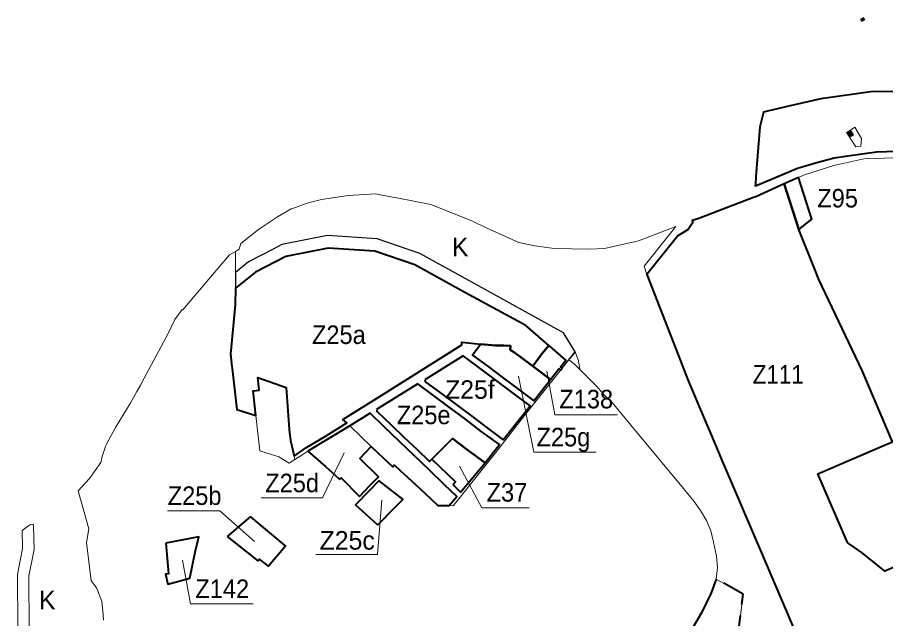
# Model space of a CAD drawing. Extents: x -650276 to -642489, y -1074425 to -1066658.
# Drawn here: x -650276 to -649154, y -1069854 to -1069075 of the extents above; entities that cross this region are included whole.
import ezdxf

# ---------------------------------------------------------------- set-up
doc = ezdxf.new("R2010")
doc.units = 0
doc.header["$LTSCALE"] = 9.6
doc.linetypes.add('MEDIUM_DASHED', pattern=[4.5, 3, -1.5])
for name, color, linetype, lineweight in [('1', 7, 'Continuous', 13), ('4', 7, 'Continuous', 40), ('42', 7, 'Continuous', 25), ('43', 7, 'Continuous', 13), ('44', 7, 'Continuous', 40), ('45', 7, 'Continuous', 40), ('46', 7, 'Continuous', 13), ('47', 7, 'Continuous', 13), ('61', 7, 'MEDIUM_DASHED', 40)]:
    doc.layers.add(name, color=color, linetype=linetype, lineweight=lineweight)

msp = doc.modelspace()

# ---------------------------------------------------------------- hatches: boundary and pattern name
at = {"layer": '1'}
for points in [[(-649180.56, -1069078.55), (-649182.45, -1069075.37), (-649186.32, -1069077.67), (-649184.43, -1069080.85)], [(-649199.29, -1069230.06), (-649195.38, -1069227.23), (-649199.26, -1069221.16), (-649203.42, -1069223.85)]]:
    msp.add_hatch(color=256, dxfattribs=at).paths.add_polyline_path(points)

# ---------------------------------------------------------------- linework, layer by layer
for points in [[(-649180.56, -1069078.55), (-649182.45, -1069075.37), (-649186.32, -1069077.67), (-649184.43, -1069080.85)], [(-649199.29, -1069230.06), (-649195.38, -1069227.23), (-649199.26, -1069221.16), (-649203.42, -1069223.85)]]:
    msp.add_lwpolyline(points, close=True, dxfattribs=at)
for points in [[(-649199.258, -1069221.162), (-649195.38, -1069227.23), (-649199.29, -1069230.06), (-649203.42, -1069223.85)], [(-649191.99, -1069242.79), (-649185.55, -1069242.21), (-649185.05, -1069232.01), (-649193.51, -1069217.45), (-649199.258, -1069221.162)], [(-649203.42, -1069223.85), (-649204.21, -1069224.36), (-649191.99, -1069242.79)], [(-649142.11, -1069257.07), (-649181.7, -1069258.52), (-649220.57, -1069266.88), (-649258.6, -1069279.34), (-649266.331, -1069282.804), (-649249.069, -1069336.66), (-649265.774, -1069350.068), (-649240.202, -1069414.528), (-649184.1, -1069532.2), (-649144.57, -1069624.6), (-649241.11, -1069665.9), (-649202.99, -1069754.99), (-649200.64, -1069756.53), (-649184.05, -1069768.45), (-649154.76, -1069792.11), (-649085.41, -1069762.44)], [(-649700.42, -1069691.8), (-649712.64, -1069707.43), (-649732.52, -1069706.92), (-649788.91, -1069654.4), (-649791.3, -1069657.21), (-649818.71, -1069630.64), (-649846.38, -1069603.8), (-649900.64, -1069636.78), (-649907.07, -1069640.92), (-649917.38, -1069647.56), (-649924.8, -1069652.19), (-649938.2, -1069644.23), (-649962.71, -1069636.46), (-649967.81, -1069590.74), (-649992.59, -1069582.88), (-649998.5, -1069529.88), (-650000.59, -1069511.15), (-649994.26, -1069444.75), (-649994.329, -1069405.451), (-649994.38, -1069378.33), (-650002.11, -1069382.8), (-650026.33, -1069411.47), (-650057.49, -1069448.18), (-650062.17, -1069454.05), (-650063.12, -1069453.54), (-650072.5, -1069466.44), (-650081.29, -1069484.35), (-650112.18, -1069542.11), (-650117.19, -1069551.46), (-650121.59, -1069559.59), (-650125.94, -1069567.19), (-650130.57, -1069575.27), (-650149.19, -1069606.26), (-650152.96, -1069612.53), (-650160.4, -1069626.97), (-650162.1, -1069630.49), (-650163.17, -1069633.49), (-650166.77, -1069643.52), (-650168.4, -1069651.27), (-650182.78, -1069672.09), (-650197.7, -1069688.08), (-650183.73, -1069737.28), (-650186.91, -1069755.15), (-650180.63, -1069804.63), (-650176.1, -1069810.74), (-650173.87, -1069813.75), (-650172.79, -1069816.55), (-650167.17, -1069831.25), (-650165.14, -1069847.93), (-650165.06, -1069855.42)], [(-649406.53, -1069871.59), (-649391.86, -1069846.18), (-649379.19, -1069820.24), (-649372.56, -1069802.33), (-649370.94, -1069787.45), (-649372.2, -1069772.58), (-649376.01, -1069754.58), (-649379.49, -1069740.04), (-649385.25, -1069726.48), (-649392.85, -1069713.53), (-649401.77, -1069701.47), (-649415.12, -1069685.26), (-649474.46, -1069613.59), (-649507.23, -1069573.85), (-649517.81, -1069563.27), (-649527.84, -1069552.16), (-649538.49, -1069541.54), (-649549.69, -1069530.14), (-649556.25, -1069523.62), (-649563.306, -1069518.507), (-649620.45, -1069590.75), (-649658.13, -1069638.84), (-649700.42, -1069691.8)], [(-649917.38, -1069647.56), (-649918.35, -1069643.45), (-649923.17, -1069623.14), (-649924.62, -1069608.53), (-649927.3, -1069572.44), (-649928.48, -1069554.57), (-649965.26, -1069541.51), (-649963.43, -1069557.91), (-649971.38, -1069558.79), (-649967.81, -1069590.74), (-649962.71, -1069636.46)], [(-649962.71, -1069636.46), (-649938.2, -1069644.23), (-649924.8, -1069652.19), (-649917.38, -1069647.56)]]:
    msp.add_lwpolyline(points, dxfattribs=at)
at = {"layer": '4'}
for points in [[(-649571.94, -1069529.24), (-649573.922, -1069527.657), (-649567, -1069519), (-649588, -1069501), (-649589.257, -1069499.905), (-649597.935, -1069510.728)], [(-649597.997, -1069510.805), (-649598.004, -1069510.814), (-649609.93, -1069526.87), (-649586.82, -1069544.11)], [(-649597.935, -1069510.728), (-649597.763, -1069510.865), (-649597.997, -1069510.805)], [(-649586.82, -1069544.11), (-649576.071, -1069530.398), (-649574.1, -1069531.97), (-649571.94, -1069529.24)], [(-650053.2, -1069801.11), (-650046.28, -1069767.47), (-650041.591, -1069747.598), (-650084.48, -1069755.86)], [(-650084.48, -1069755.86), (-650082.63, -1069775.78), (-650080.78, -1069795.7), (-650084.63, -1069796.06), (-650081.66, -1069808.87), (-650053.2, -1069801.11)]]:
    msp.add_lwpolyline(points, dxfattribs=at)
at = {"layer": '4', "lineweight": 13}
for points in [[(-649500.234, -1069589.798), (-649581.154, -1069589.798), (-649591.594, -1069533.245)], [(-649971.531, -1069834.438), (-650052.451, -1069834.438), (-650062.891, -1069777.884)]]:
    msp.add_lwpolyline(points, dxfattribs=at)
at = {"layer": '42'}
msp.add_lwpolyline([(-649561.91, -1069516.78), (-649555.16, -1069508.07), (-649570.03, -1069483.83), (-649688.625, -1069418.156), (-649755.971, -1069381.179), (-649810.846, -1069362.154), (-649875.434, -1069357.751), (-649934.363, -1069369.537), (-649945.397, -1069375.277), (-649977.239, -1069391.714), (-649994.329, -1069405.451), (-649994.293, -1069425.949), (-649994.53, -1069447.61), (-650000.59, -1069511.15), (-649992.59, -1069582.88), (-649967.81, -1069590.74), (-649971.38, -1069558.79), (-649963.43, -1069557.91), (-649965.26, -1069541.51), (-649928.48, -1069554.57), (-649924.62, -1069608.53), (-649923.17, -1069623.14), (-649918.35, -1069643.45), (-649903.292, -1069632.541), (-649877.129, -1069617.006), (-649850.24, -1069600.295), (-649855.34, -1069595.8), (-649805.22, -1069564.32), (-649701.57, -1069499.21), (-649701.7, -1069495.89), (-649677.02, -1069498.32), (-649658.01, -1069500.19), (-649647.45, -1069500.23), (-649638.81, -1069500.26), (-649639.18, -1069505.96), (-649628.36, -1069513.11), (-649609.93, -1069526.87), (-649598.004, -1069510.814), (-649589.257, -1069499.905), (-649567, -1069519), (-649573.922, -1069527.657), (-649571.94, -1069529.24), (-649555.16, -1069508.07)], close=True, dxfattribs=at)
at = {"layer": '44'}
msp.add_lwpolyline([(-649076.02, -1069172.683), (-649169.781, -1069171.432), (-649237.512, -1069180.731), (-649277.021, -1069189.913), (-649306.455, -1069196.754), (-649311.633, -1069197.958), (-649316.47, -1069216.91), (-649321.32, -1069281.47), (-649322.09, -1069291.73), (-649322.22, -1069293.54), (-649319.72, -1069292.47), (-649267.5, -1069270.41), (-649242.5, -1069263.3), (-649220.18, -1069257.03), (-649202.63, -1069254.4), (-649165.62, -1069249.43), (-649139.63, -1069248.73)], dxfattribs=at)
msp.add_lwpolyline([(-649265.774, -1069350.068), (-649249.069, -1069336.66), (-649266.331, -1069282.804), (-649284.695, -1069291.033)], close=True, dxfattribs=at)
at = {"layer": '45'}
for points in [[(-649099.75, -1069768.575), (-649154.76, -1069792.11), (-649184.05, -1069768.45), (-649200.64, -1069756.53), (-649202.99, -1069754.99), (-649241.11, -1069665.9), (-649155.082, -1069629.097), (-649144.57, -1069624.6), (-649184.1, -1069532.2), (-649240.202, -1069414.528), (-649244.08, -1069404.753), (-649265.774, -1069350.068), (-649284.695, -1069291.033), (-649321.69, -1069307.61), (-649324.3, -1069308.59), (-649359.48, -1069321.82), (-649389.4, -1069333.35), (-649396.52, -1069336.09), (-649403.92, -1069338.26), (-649403.03, -1069340.66), (-649408.81, -1069349.89), (-649422.19, -1069357.99), (-649462.25, -1069408.32), (-649435.578, -1069476.772), (-649435.578, -1069476.772), (-649431.761, -1069486.57), (-649416.52, -1069525.68), (-649409.355, -1069544.517), (-649388.438, -1069594.296), (-649379.32, -1069615.71), (-649364.44, -1069650.55), (-649312.03, -1069773.33), (-649246.81, -1069926.27)], [(-649639.18, -1069505.96), (-649637.69, -1069506.15), (-649628.36, -1069513.11), (-649609.93, -1069526.87), (-649598.004, -1069510.814), (-649589.257, -1069499.905), (-649619, -1069474), (-649697.525, -1069431.522), (-649762.488, -1069395.854), (-649814.067, -1069377.972), (-649874.391, -1069373.859), (-649929.015, -1069384.784), (-649968.465, -1069405.189), (-649994.293, -1069425.949), (-649994.53, -1069447.61), (-650000.59, -1069511.15), (-649998.81, -1069527.07), (-649998.5, -1069529.88), (-649992.59, -1069582.88), (-649967.81, -1069590.74), (-649971.38, -1069558.79), (-649963.43, -1069557.91), (-649965.26, -1069541.51), (-649928.48, -1069554.57), (-649927.3, -1069572.44)], [(-649927.3, -1069572.44), (-649924.62, -1069608.53), (-649923.17, -1069623.14), (-649918.35, -1069643.45), (-649918.35, -1069643.45), (-649903.292, -1069632.541), (-649877.129, -1069617.006), (-649850.24, -1069600.295), (-649855.34, -1069595.8), (-649805.22, -1069564.32), (-649801.49, -1069561.98), (-649701.57, -1069499.21), (-649701.7, -1069495.89), (-649677.02, -1069498.32), (-649658.01, -1069500.19), (-649647.45, -1069500.23), (-649638.81, -1069500.26), (-649639.18, -1069505.96)], [(-649677.02, -1069498.32), (-649687.77, -1069512.44), (-649667.74, -1069527.4), (-649649.31, -1069541.16)], [(-649639.18, -1069505.96), (-649638.81, -1069500.26), (-649647.45, -1069500.23), (-649658.01, -1069500.19), (-649677.02, -1069498.32)], [(-649609.93, -1069526.87), (-649628.36, -1069513.11), (-649637.69, -1069506.15), (-649639.18, -1069505.96)], [(-649707.19, -1069577.81), (-649688.76, -1069591.57), (-649670.34, -1069605.34), (-649647.93, -1069622.07), (-649628.8, -1069597.67), (-649613.37, -1069577.98), (-649636.83, -1069560.47), (-649659.26, -1069543.71), (-649681.7, -1069526.96), (-649699.72, -1069513.5), (-649722.6, -1069527.61), (-649749.62, -1069544.29)], [(-649649.31, -1069541.16), (-649630.88, -1069554.92), (-649608.44, -1069571.69), (-649586.82, -1069544.11), (-649609.93, -1069526.87)], [(-649749.62, -1069544.29), (-649748.89, -1069546.2), (-649747.5, -1069547.71), (-649725.62, -1069564.05), (-649707.19, -1069577.81)], [(-649758.29, -1069549.64), (-649785.72, -1069566.56), (-649812.08, -1069582.83)], [(-649671.39, -1069651.93), (-649652.88, -1069628.36), (-649677.124, -1069610.681), (-649696.91, -1069595.47), (-649718.13, -1069579.63), (-649739.75, -1069563.48), (-649758.29, -1069549.64)], [(-649788.91, -1069654.4), (-649781.09, -1069661.69), (-649761.34, -1069680.08), (-649741.61, -1069698.46), (-649732.52, -1069706.92), (-649717.884, -1069707.295), (-649707.985, -1069695.508), (-649723.97, -1069680.13), (-649743.41, -1069661.43), (-649762.85, -1069642.73), (-649782.03, -1069624.28), (-649801.48, -1069605.57), (-649820.02, -1069587.73), (-649846.38, -1069603.8), (-649900.64, -1069636.78)], [(-649812.08, -1069582.83), (-649811.52, -1069584.44), (-649810.49, -1069585.81), (-649793.12, -1069602.51), (-649776.54, -1069618.46), (-649759.97, -1069634.4)], [(-649740.23, -1069647.14), (-649713.73, -1069620.32), (-649713.73, -1069620.32), (-649693.63, -1069635.33), (-649671.39, -1069651.93)], [(-649900.64, -1069636.78), (-649877.82, -1069656.83), (-649859.96, -1069672.53)], [(-649833.94, -1069695.239), (-649819.98, -1069680.92), (-649809.47, -1069670.13), (-649833.38, -1069646.08), (-649818.71, -1069630.64)], [(-649818.71, -1069630.64), (-649802.9, -1069645.96), (-649791, -1069657), (-649788.91, -1069654.4)], [(-649759.97, -1069634.4), (-649743.39, -1069650.35), (-649740.23, -1069647.14)], [(-649859.96, -1069672.53), (-649859.17, -1069673.22), (-649857.49, -1069671.46), (-649833.94, -1069695.239)]]:
    msp.add_lwpolyline(points, dxfattribs=at)
for points in [[(-649713.73, -1069620.32), (-649713.73, -1069620.32), (-649740.23, -1069647.14), (-649709.94, -1069676.28), (-649712.54, -1069678.98), (-649712.89, -1069679.87), (-649712.51, -1069680.75), (-649703.15, -1069689.75), (-649671.39, -1069651.93), (-649693.63, -1069635.33)], [(-649838.99, -1069706.15), (-649820.64, -1069687.33), (-649808.96, -1069675.34), (-649777.94, -1069699.2), (-649792.13, -1069713.65), (-649807.66, -1069729.46), (-649810.41, -1069732.28), (-649819.9, -1069723.61)], [(-650004.59, -1069747.27), (-649974.86, -1069721.96), (-649966.52, -1069728.87), (-649929.38, -1069759.65), (-649951.56, -1069785.42), (-649963, -1069776.7), (-649965, -1069778.7)]]:
    msp.add_lwpolyline(points, close=True, dxfattribs=at)
at = {"layer": '46'}
for points in [[(-649527.746, -1069637.974), (-649608.666, -1069637.974), (-649628.441, -1069539.635)], [(-649961.194, -1069696.966), (-649881.648, -1069696.966), (-649853.499, -1069639.046), (-649881.648, -1069696.966), (-649881.648, -1069696.966)], [(-649614.407, -1069710.017), (-649675.69, -1069710.017), (-649704.435, -1069656.13)], [(-649890.273, -1069770.557), (-649810.727, -1069770.557), (-649804.906, -1069700.153), (-649810.727, -1069770.557), (-649810.727, -1069770.557)], [(-650082.06, -1069714.05), (-650014.296, -1069714.05), (-650014.296, -1069714.05), (-649969.577, -1069753.88)]]:
    msp.add_lwpolyline(points, dxfattribs=at)
at = {"layer": '47'}
for points in [[(-649509.42, -1069372.61), (-649517.17, -1069374.3), (-649537.32, -1069375.23), (-649582.25, -1069374.51), (-649607.18, -1069370.92), (-649627.76, -1069366.8), (-649645.03, -1069358.8), (-649670.23, -1069347.9), (-649688.73, -1069338.7), (-649690.59, -1069337.98), (-649741.5, -1069317.74), (-649785.8, -1069308.94), (-649789, -1069308.31), (-649813.3, -1069303.66), (-649848.62, -1069305.95), (-649882.93, -1069311.1), (-649901.58, -1069316.01), (-649921.54, -1069323.03), (-649922.11, -1069323.35), (-649939.81, -1069333.47), (-649964.53, -1069350.02), (-649987.12, -1069368.03), (-649989.67, -1069375.36), (-649994.38, -1069378.33), (-649994.35, -1069394.43), (-649994.34, -1069398.8), (-649994.329, -1069405.451), (-649977.239, -1069391.714), (-649945.397, -1069375.277), (-649934.363, -1069369.537), (-649875.434, -1069357.751), (-649810.846, -1069362.154), (-649755.971, -1069381.179), (-649688.625, -1069418.156), (-649570.03, -1069483.83)], [(-649424.8, -1069346.14), (-649438.17, -1069351.27), (-649473.35, -1069364.76), (-649473.35, -1069364.76), (-649509.42, -1069372.61)], [(-649431.761, -1069486.57), (-649435.578, -1069476.772), (-649435.578, -1069476.772), (-649462.25, -1069408.32), (-649466.045, -1069397.373), (-649424.8, -1069346.14)], [(-649570.03, -1069483.83), (-649555.16, -1069508.07), (-649550.53, -1069519.68)], [(-649409.349, -1069544.532), (-649409.355, -1069544.517), (-649416.52, -1069525.68), (-649431.761, -1069486.57)], [(-649550.53, -1069519.68), (-649548.881, -1069530.963), (-649538.49, -1069541.54)], [(-649538.49, -1069541.54), (-649527.84, -1069552.16), (-649517.81, -1069563.27), (-649507.23, -1069573.85), (-649474.46, -1069613.59), (-649415.12, -1069685.26), (-649401.77, -1069701.47), (-649392.85, -1069713.53), (-649385.25, -1069726.48), (-649379.49, -1069740.04), (-649376.01, -1069754.58), (-649372.2, -1069772.58), (-649370.94, -1069787.45), (-649372.56, -1069802.33), (-649372.56, -1069802.33), (-649338, -1069822), (-649350.222, -1069920.873), (-649310.738, -1069929.342), (-649296.851, -1069931.092)], [(-649379.32, -1069615.71), (-649407.002, -1069550.701), (-649409.349, -1069544.532)], [(-649202.375, -1070030.469), (-649239.635, -1069943.094), (-649246.81, -1069926.27), (-649246.81, -1069926.27), (-649312.03, -1069773.33), (-649364.44, -1069650.55), (-649379.32, -1069615.71)], [(-650260.665, -1069868.303), (-650260.748, -1069867.327), (-650261.204, -1069797.969), (-650254.411, -1069764.006), (-650255.21, -1069733.253), (-650255.716, -1069731.162), (-650259.97, -1069732.29), (-650264.91, -1069735.69), (-650270.059, -1069739.232)], [(-650270.059, -1069739.232), (-650269.449, -1069762.714), (-650276.214, -1069796.532), (-650275.76, -1069865.474), (-650274.95, -1069865.62)]]:
    msp.add_lwpolyline(points, dxfattribs=at)
at = {"layer": '61'}
msp.add_lwpolyline([(-649372.56, -1069802.33), (-649379.19, -1069820.24), (-649391.86, -1069846.18), (-649406.53, -1069871.59), (-649417.234, -1069885.193), (-649350.222, -1069920.873), (-649338, -1069822)], close=True, dxfattribs=at)

# ---------------------------------------------------------------- texts
at = {"layer": '4', "width": 0.95}
for s, p in [('Z138', (-649575.524, -1069581.383)), ('Z142', (-650046.077, -1069826.766))]:
    msp.add_text(s, height=24, dxfattribs=at).set_placement(p)
at = {"layer": '43'}
for p in [(-649714.485, -1069384.456), (-649714.485, -1069384.456), (-650248.205, -1069841.413), (-650248.205, -1069841.413)]:
    msp.add_text('K', height=24, dxfattribs=at).set_placement(p)
at = {"layer": '44', "width": 0.95}
msp.add_text('Z95', height=24, dxfattribs=at).set_placement((-649242.024, -1069321.399))
at = {"layer": '46'}
for s, width, p in [('Z25a', 0.95, (-649895.305, -1069498.073)), ('Z111', 0.9, (-649325.444, -1069549.35)), ('Z111', 0.9, (-649325.444, -1069549.35)), ('Z25e', 0.95, (-649785.641, -1069601.889)), ('Z25g', 0.95, (-649605.002, -1069630.542)), ('Z25d', 0.95, (-649955.718, -1069689.936)), ('Z25b', 0.95, (-650081.8, -1069706.363)), ('Z37', 0.95, (-649669.466, -1069702.084))]:
    msp.add_text(s, height=24, dxfattribs=dict(at, width=width)).set_placement(p)
for s, p in [('Z25f', (-649723.257, -1069569.036)), ('Z25c', (-649885.454, -1069764.184))]:
    msp.add_text(s, height=24, dxfattribs=at).set_placement(p)

doc.saveas('drawing.dxf')
